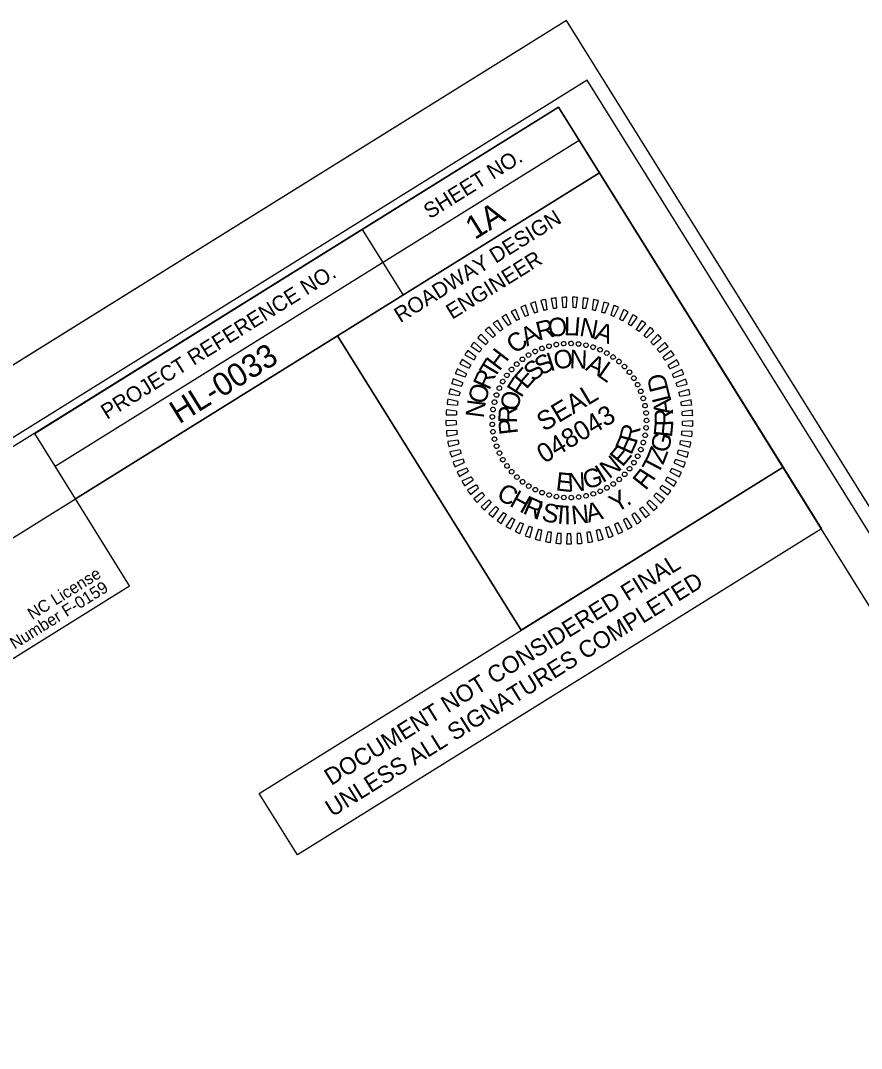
# Model space of a CAD drawing. Extents: x 2047559 to 2049567, y 759970 to 761789.
# Drawn here: x 2048811.1 to 2049083.6, y 761456 to 761789.3 of the extents above; entities that cross this region are included whole.
import ezdxf

# ---------------------------------------------------------------- set-up
doc = ezdxf.new("R2010")
doc.units = 0
for name, color, linetype in [('Default', 7, 'Continuous'), ('Old_Level_4', 7, 'Continuous'), ('Sheet Cutting Line CELL', 7, 'Continuous'), ('Sheet Data Field CELL', 7, 'Continuous'), ('Sheet PE Seal Cell', 7, 'Continuous'), ('Sheet Plan CELL', 7, 'Continuous'), ('Sheet Plot Border Inside CELL', 7, 'Continuous'), ('Sheet Plot Border Outside CELL', 7, 'Continuous'), ('Sheet Sticker Exception Certification CELL', 7, 'Continuous')]:
    doc.layers.add(name, color=color, linetype=linetype)

msp = doc.modelspace()

# ---------------------------------------------------------------- linework, layer by layer
at = {"layer": 'Default'}
msp.add_line((2048693.02, 761549.62), (2048828.87, 761634.21), dxfattribs=at)
at = {"layer": 'Old_Level_4'}
for p, q in [((2048846.4, 761606.07), (2048828.87, 761634.21)), ((2048710.56, 761521.46), (2048846.4, 761606.07))]:
    msp.add_line(p, q, dxfattribs=at)
at = {"layer": 'Sheet Cutting Line CELL'}
msp.add_line((2048987.97, 761789.33), (2047559, 760899.25), dxfattribs=at)
at = {"layer": 'Sheet PE Seal Cell'}
for p, q in [((2048975.68, 761693.81), (2048974.65, 761697.01)), ((2048976.34, 761697.61), (2048977.57, 761694.48)), ((2048978.67, 761694.82), (2048977.92, 761698.09)), ((2048979.65, 761698.55), (2048980.61, 761695.33)), ((2048981.73, 761695.57), (2048981.27, 761698.89)), ((2048983.03, 761699.2), (2048983.7, 761695.91)), ((2048984.85, 761696.06), (2048984.67, 761699.41)), ((2048986.46, 761699.56), (2048986.84, 761696.22)), ((2048987.99, 761696.27), (2048988.11, 761699.62)), ((2048989.9, 761699.62), (2048990, 761696.26)), ((2048991.14, 761696.21), (2048991.55, 761699.54)), ((2048993.33, 761699.39), (2048993.14, 761696.04)), ((2048994.28, 761695.88), (2048994.97, 761699.17)), ((2048996.73, 761698.86), (2048996.26, 761695.54)), ((2048997.38, 761695.29), (2048998.34, 761698.5)), ((2049000.08, 761698.04), (2048999.31, 761694.77)), ((2049000.41, 761694.43), (2049001.65, 761697.55)), ((2049003.34, 761696.94), (2049002.3, 761693.75)), ((2048970.02, 761691.04), (2048968.46, 761694.01)), ((2048970.02, 761694.89), (2048971.77, 761692.03)), ((2048972.79, 761692.55), (2048971.49, 761695.64)), ((2048973.13, 761696.39), (2048974.61, 761693.38)), ((2049003.36, 761693.31), (2049004.86, 761696.31)), ((2049006.49, 761695.56), (2049005.18, 761692.47)), ((2049006.2, 761691.94), (2049007.96, 761694.8)), ((2049009.51, 761693.91), (2049007.94, 761690.95)), ((2048964.92, 761687.34), (2048962.88, 761690)), ((2048964.26, 761691.14), (2048966.47, 761688.61)), ((2048967.39, 761689.3), (2048965.58, 761692.13)), ((2048967.06, 761693.14), (2048969.04, 761690.43)), ((2049008.92, 761690.34), (2049010.91, 761693.04)), ((2049012.38, 761692.02), (2049010.56, 761689.2)), ((2049011.48, 761688.5), (2049013.7, 761691.02)), ((2048962.63, 761685.18), (2048960.36, 761687.65)), ((2048961.65, 761688.9), (2048964.06, 761686.57)), ((2049015.08, 761689.88), (2049013.03, 761687.23)), ((2049013.88, 761686.46), (2049016.31, 761688.77)), ((2049017.59, 761687.52), (2049015.31, 761685.05)), ((2048957.03, 761683.8), (2048959.81, 761681.92)), ((2048960.53, 761682.82), (2048958.06, 761685.09)), ((2048959.23, 761686.45), (2048961.84, 761684.34)), ((2049016.09, 761684.21), (2049018.71, 761686.31)), ((2049019.88, 761684.95), (2049017.4, 761682.69)), ((2049018.11, 761681.78), (2049020.89, 761683.65)), ((2048955.07, 761680.97), (2048958.01, 761679.34)), ((2048958.64, 761680.3), (2048955.98, 761682.35)), ((2049021.94, 761682.19), (2049019.27, 761680.15)), ((2049019.9, 761679.19), (2049022.84, 761680.81)), ((2048953.37, 761677.98), (2048956.43, 761676.61)), ((2048956.97, 761677.62), (2048954.15, 761679.43)), ((2049023.75, 761679.27), (2049020.92, 761677.47)), ((2049021.47, 761676.45), (2049024.53, 761677.81)), ((2048951.92, 761674.86), (2048955.09, 761673.75)), ((2048955.55, 761674.81), (2048952.58, 761676.37)), ((2049025.31, 761676.2), (2049022.34, 761674.65)), ((2049022.79, 761673.59), (2049025.97, 761674.68)), ((2048950.75, 761671.62), (2048954, 761670.79)), ((2048954.36, 761671.88), (2048951.27, 761673.19)), ((2049026.6, 761673.01), (2049023.51, 761671.72)), ((2049023.87, 761670.63), (2049027.12, 761671.44)), ((2048949.86, 761668.3), (2048953.17, 761667.75)), ((2048953.44, 761668.87), (2048950.25, 761669.9)), ((2049027.61, 761669.72), (2049024.42, 761668.7)), ((2049024.68, 761667.58), (2049028, 761668.11)), ((2048949.26, 761664.91), (2048952.6, 761664.65)), ((2048952.78, 761665.78), (2048949.51, 761666.54)), ((2049028.34, 761666.35), (2049025.07, 761665.61)), ((2049025.24, 761664.47), (2049028.58, 761664.72)), ((2048948.95, 761661.48), (2048952.3, 761661.51)), ((2048952.38, 761662.66), (2048949.06, 761663.13)), ((2049028.77, 761662.94), (2049025.45, 761662.48)), ((2049025.52, 761661.33), (2049028.87, 761661.29)), ((2048952.26, 761659.51), (2048948.91, 761659.69)), ((2048948.94, 761658.04), (2048952.28, 761658.36)), ((2048988.91, 761659.63), (2048988.91, 761659.63)), ((2049025.53, 761658.18), (2049028.87, 761657.85)), ((2049028.91, 761659.5), (2049025.56, 761659.33)), ((2048952.4, 761656.35), (2048949.05, 761656.25)), ((2048949.22, 761654.61), (2048952.52, 761655.21)), ((2049025.27, 761655.04), (2049028.57, 761654.42)), ((2049028.75, 761656.06), (2049025.39, 761656.18)), ((2048952.82, 761653.23), (2048949.49, 761652.84)), ((2048949.8, 761651.22), (2048953.04, 761652.1)), ((2048953.5, 761650.15), (2048950.22, 761649.47)), ((2049027.55, 761649.29), (2049024.26, 761649.98)), ((2049024.74, 761651.93), (2049027.97, 761651.03)), ((2049028.29, 761652.65), (2049024.96, 761653.06)), ((2048950.67, 761647.89), (2048953.82, 761649.04)), ((2048954.45, 761647.14), (2048951.23, 761646.19)), ((2049026.51, 761646.01), (2049023.3, 761646.98)), ((2049023.94, 761648.88), (2049027.09, 761647.71)), ((2048951.82, 761644.64), (2048954.86, 761646.07)), ((2048955.65, 761644.23), (2048952.53, 761643)), ((2049025.2, 761642.82), (2049022.09, 761644.07)), ((2049022.89, 761645.9), (2049025.92, 761644.47)), ((2048953.25, 761641.51), (2048956.15, 761643.19)), ((2048957.1, 761641.42), (2048954.09, 761639.93)), ((2048954.94, 761638.51), (2048957.69, 761640.44)), ((2049020.04, 761640.29), (2049022.78, 761638.35)), ((2049023.63, 761639.77), (2049020.63, 761641.27)), ((2049021.58, 761643.03), (2049024.48, 761641.34)), ((2048958.78, 761638.76), (2048955.92, 761637.01)), ((2048956.88, 761635.67), (2048959.45, 761637.82)), ((2049018.26, 761637.68), (2049020.82, 761635.52)), ((2049021.79, 761636.86), (2049018.93, 761638.61)), ((2048960.69, 761636.25), (2048957.98, 761634.26)), ((2048959.05, 761633.01), (2048961.43, 761635.37)), ((2048962.8, 761633.91), (2048960.28, 761631.7)), ((2049017.4, 761631.56), (2049014.89, 761633.78)), ((2049016.26, 761635.24), (2049018.63, 761632.86)), ((2049019.71, 761634.11), (2049017.01, 761636.11)), ((2048961.45, 761630.54), (2048963.62, 761633.1)), ((2048965.11, 761631.76), (2048962.79, 761629.34)), ((2048964.06, 761628.29), (2048966, 761631.02)), ((2049011.68, 761630.92), (2049013.61, 761628.17)), ((2049014.88, 761629.21), (2049012.57, 761631.64)), ((2049014.06, 761632.98), (2049016.22, 761630.41)), ((2048967.59, 761629.81), (2048965.49, 761627.2)), ((2048966.84, 761626.27), (2048968.54, 761629.16)), ((2048970.24, 761628.09), (2048968.36, 761625.31)), ((2048969.79, 761624.49), (2048971.24, 761627.52)), ((2049006.42, 761627.44), (2049007.85, 761624.4)), ((2049009.29, 761625.21), (2049007.43, 761628)), ((2049009.13, 761629.06), (2049010.81, 761626.16)), ((2049012.17, 761627.09), (2049010.08, 761629.71)), ((2048973.02, 761626.6), (2048971.39, 761623.67)), ((2048972.88, 761622.98), (2048974.06, 761626.12)), ((2048975.91, 761625.36), (2048974.54, 761622.3)), ((2048976.09, 761621.74), (2048977, 761624.97)), ((2048978.91, 761624.37), (2048977.81, 761621.2)), ((2048979.4, 761620.78), (2048980.02, 761624.07)), ((2048981.98, 761623.64), (2048981.15, 761620.39)), ((2048982.77, 761620.1), (2048983.11, 761623.44)), ((2048994.53, 761623.42), (2048994.85, 761620.08)), ((2048996.48, 761620.35), (2048995.66, 761623.61)), ((2048997.62, 761624.03), (2048998.23, 761620.73)), ((2048999.82, 761621.15), (2048998.74, 761624.32)), ((2049000.65, 761624.91), (2049001.54, 761621.68)), ((2049003.09, 761622.23), (2049001.73, 761625.3)), ((2049003.59, 761626.05), (2049004.75, 761622.9)), ((2049006.25, 761623.59), (2049004.64, 761626.53)), ((2048985.1, 761623.18), (2048984.55, 761619.87)), ((2048986.2, 761619.72), (2048986.24, 761623.08)), ((2048988.24, 761622.99), (2048987.99, 761619.64)), ((2048989.64, 761619.64), (2048989.39, 761622.98)), ((2048991.4, 761623.07), (2048991.43, 761619.71)), ((2048993.07, 761619.85), (2048992.54, 761623.16))]:
    msp.add_line(p, q, dxfattribs=at)
for radius, start, end in [(40, 110.8732, 113.2368), (40, 105.9417, 108.3053), (40, 101.0102, 103.3738), (40, 96.0787, 98.4423), (40, 91.1472, 93.5108), (40, 86.2157, 88.5793), (40, 81.2842, 83.6478), (40, 76.3527, 78.7163), (40, 71.4212, 73.7848), (40, 66.4896, 68.8533), (40, 120.7362, 123.0998), (40, 115.8047, 118.1683), (36.65, 111.1561, 112.954), (36.65, 106.2246, 108.0225), (36.65, 101.2931, 103.091), (36.65, 96.3616, 98.1594), (36.65, 91.43, 93.2279), (36.65, 86.4985, 88.2964), (36.65, 81.567, 83.3649), (36.65, 76.6355, 78.4334), (36.65, 71.704, 73.5019), (36.65, 66.7725, 68.5704), (40, 61.5581, 63.9218), (40, 56.6266, 58.9903), (40, 130.5992, 132.9629), (40, 125.6677, 128.0313), (36.65, 121.0191, 122.817), (36.65, 116.0876, 117.8855), (36.65, 61.841, 63.6389), (36.65, 56.9095, 58.7074), (40, 51.6951, 54.0587), (40, 135.5307, 137.8944), (36.65, 130.8821, 132.68), (36.65, 125.9506, 127.7485), (36.65, 51.978, 53.7759), (36.65, 47.0465, 48.8444), (40, 46.7636, 49.1272), (40, 41.8321, 44.1957), (40, 140.4623, 142.8259), (36.65, 135.8136, 137.6115), (36.65, 42.115, 43.9129), (40, 36.9006, 39.2642), (40, 145.3938, 147.7574), (36.65, 145.6766, 147.4745), (36.65, 140.7451, 142.543), (36.65, 37.1835, 38.9814), (36.65, 32.252, 34.0499), (40, 31.9691, 34.3327), (40, 150.3253, 152.6889), (36.65, 150.6081, 152.406), (36.65, 27.3205, 29.1184), (40, 27.0376, 29.4012), (40, 155.2568, 157.6204), (36.65, 155.5396, 157.3375), (36.65, 22.3889, 24.1868), (40, 22.1061, 24.4697), (40, 160.1883, 162.5519), (36.65, 160.4711, 162.269), (36.65, 17.4574, 19.2553), (40, 17.1746, 19.5382), (40, 165.1198, 167.4834), (36.65, 165.4026, 167.2005), (36.65, 12.5259, 14.3238), (40, 12.2431, 14.6067), (40, 170.0513, 172.4149), (36.65, 170.3342, 172.132), (36.65, 7.5944, 9.3923), (40, 7.3116, 9.6752), (40, 174.9828, 177.3464), (36.65, 175.2657, 177.0636), (36.65, 2.6629, 4.4608), (40, 2.3801, 4.7437), (40, 179.9143, 182.2779), (36.65, 180.1972, 181.9951), (36.65, 357.7314, 359.5293), (40, 357.4486, 359.8122), (40, 184.8458, 187.2094), (36.65, 185.1287, 186.9266), (36.65, 352.7999, 354.5978), (40, 352.517, 354.8807), (40, 189.7773, 192.1409), (36.65, 190.0602, 191.8581), (36.65, 194.9917, 196.7896), (36.65, 342.9369, 344.7348), (36.65, 347.8684, 349.6663), (40, 347.5855, 349.9492), (40, 194.7088, 197.0724), (36.65, 199.9232, 201.7211), (36.65, 338.0054, 339.8033), (40, 342.654, 345.0177), (40, 199.6403, 202.004), (36.65, 204.8547, 206.6526), (36.65, 333.0739, 334.8718), (40, 337.7225, 340.0861), (40, 204.5718, 206.9355), (36.65, 209.7862, 211.5841), (36.65, 328.1424, 329.9403), (40, 332.791, 335.1546), (40, 209.5033, 211.867), (40, 214.4349, 216.7985), (36.65, 214.7177, 216.5156), (36.65, 323.2109, 325.0088), (40, 322.928, 325.2916), (40, 327.8595, 330.2231), (40, 219.3664, 221.73), (36.65, 219.6492, 221.4471), (36.65, 224.5807, 226.3786), (36.65, 313.3479, 315.1457), (36.65, 318.2794, 320.0773), (40, 317.9965, 320.3601), (40, 224.2979, 226.6615), (36.65, 229.5122, 231.3101), (36.65, 308.4163, 310.2142), (40, 313.065, 315.4286), (40, 229.2294, 231.593), (40, 234.1609, 236.5245), (36.65, 234.4437, 236.2416), (36.65, 239.3753, 241.1731), (36.65, 298.5533, 300.3512), (36.65, 303.4848, 305.2827), (40, 303.202, 305.5656), (40, 308.1335, 310.4971), (40, 239.0924, 241.456), (40, 244.0239, 246.3875), (36.65, 244.3068, 246.1047), (36.65, 249.2383, 251.0362), (36.65, 254.1698, 255.9677), (36.65, 259.1013, 260.8992), (36.65, 278.8273, 280.6252), (36.65, 283.7588, 285.5567), (36.65, 288.6903, 290.4882), (36.65, 293.6218, 295.4197), (40, 293.339, 295.7026), (40, 298.2705, 300.6341), (40, 248.9554, 251.319), (40, 253.8869, 256.2505), (40, 258.8184, 261.182), (36.65, 264.0328, 265.8307), (36.65, 268.9643, 270.7622), (36.65, 273.8958, 275.6937), (40, 278.5444, 280.9081), (40, 283.4759, 285.8396), (40, 288.4075, 290.7711), (40, 263.7499, 266.1135), (40, 268.6814, 271.045), (40, 273.6129, 275.9766)]:
    msp.add_arc((2048988.91, 761659.63), radius, start, end, dxfattribs=at)
for centre, major_axis in [((2048980.01, 761683), (-0.312, 0.674)), ((2048982.31, 761683.74), (-0.245, 0.701)), ((2048984.67, 761684.27), (-0.177, 0.721)), ((2048987.06, 761684.56), (-0.106, 0.735)), ((2048989.48, 761684.62), (-0.035, 0.742)), ((2048991.89, 761684.45), (0.037, 0.741)), ((2048994.27, 761684.05), (0.108, 0.734)), ((2048996.6, 761683.42), (0.179, 0.721)), ((2048998.86, 761682.56), (0.247, 0.7)), ((2048973.7, 761679.48), (-0.491, 0.556)), ((2048975.69, 761680.85), (-0.435, 0.601)), ((2048977.8, 761682.03), (-0.375, 0.64)), ((2049001.03, 761681.5), (0.314, 0.673)), ((2049003.08, 761680.22), (0.377, 0.639)), ((2048970.17, 761676.19), (-0.589, 0.452)), ((2048971.86, 761677.92), (-0.543, 0.506)), ((2049005, 761678.76), (0.437, 0.6)), ((2049006.77, 761677.12), (0.493, 0.555)), ((2048968.66, 761674.3), (-0.63, 0.393)), ((2049008.38, 761675.31), (0.544, 0.505)), ((2049009.8, 761673.36), (0.59, 0.45)), ((2048966.22, 761670.14), (-0.694, 0.264)), ((2048967.34, 761672.28), (-0.665, 0.33)), ((2049011.03, 761671.28), (0.631, 0.391)), ((2048965.31, 761667.9), (-0.716, 0.196)), ((2049012.05, 761669.09), (0.666, 0.328)), ((2049012.85, 761666.81), (0.694, 0.262)), ((2048964.16, 761663.21), (-0.74, 0.055)), ((2048964.63, 761665.58), (-0.732, 0.126)), ((2049013.43, 761664.47), (0.717, 0.194)), ((2048963.93, 761660.81), (-0.742, -0.017)), ((2049013.79, 761662.08), (0.732, 0.124)), ((2049013.91, 761659.66), (0.74, 0.053)), ((2048963.94, 761658.39), (-0.737, -0.088)), ((2048964.17, 761655.99), (-0.725, -0.159)), ((2049013.79, 761657.25), (0.742, -0.019)), ((2048964.64, 761653.62), (-0.706, -0.228)), ((2049012.87, 761652.51), (0.725, -0.161)), ((2049013.45, 761654.86), (0.737, -0.091)), ((2048965.33, 761651.3), (-0.681, -0.295)), ((2049012.07, 761650.23), (0.706, -0.23)), ((2048966.25, 761649.07), (-0.649, -0.36)), ((2048967.37, 761646.93), (-0.612, -0.421)), ((2049009.84, 761645.96), (0.648, -0.362)), ((2049011.06, 761648.04), (0.68, -0.297)), ((2048968.7, 761644.91), (-0.568, -0.478)), ((2048970.21, 761643.03), (-0.519, -0.53)), ((2049008.42, 761644), (0.61, -0.423)), ((2048971.9, 761641.3), (-0.466, -0.578)), ((2048973.75, 761639.75), (-0.408, -0.62)), ((2049005.05, 761640.54), (0.518, -0.532)), ((2049006.82, 761642.19), (0.567, -0.479)), ((2048975.74, 761638.38), (-0.346, -0.657)), ((2048977.85, 761637.21), (-0.281, -0.687)), ((2048980.07, 761636.24), (-0.213, -0.711)), ((2048996.66, 761635.86), (0.279, -0.688)), ((2048998.92, 761636.72), (0.344, -0.658)), ((2049001.08, 761637.8), (0.406, -0.622)), ((2049003.13, 761639.07), (0.464, -0.579)), ((2048982.37, 761635.5), (-0.144, -0.728)), ((2048984.73, 761634.98), (-0.073, -0.739)), ((2048987.13, 761634.69), (-0.001, -0.742)), ((2048989.54, 761634.64), (0.071, -0.739)), ((2048991.95, 761634.82), (0.142, -0.729)), ((2048994.33, 761635.23), (0.211, -0.712))]:
    msp.add_ellipse(centre, major_axis=major_axis, ratio=0.999708, dxfattribs=at)
at = {"layer": 'Sheet Plan CELL'}
for p, q in [((2048822.27, 761644.82), (2048992.07, 761750.59)), ((2048828.87, 761634.21), (2048998.68, 761739.98)), ((2048828.87, 761634.21), (2048998.68, 761739.98)), ((2048921.8, 761721.55), (2048935.02, 761700.33)), ((2048913.8, 761687.11), (2048973.25, 761591.66))]:
    msp.add_line(p, q, dxfattribs=at)
for points in [[(2048985.43, 761761.24), (2047712.23, 760968.18), (2048267.37, 760076.94), (2049540.57, 760870)], [(2048815.63, 761655.48), (2048985.43, 761761.24), (2048998.68, 761739.98), (2048828.87, 761634.21)], [(2048913.8, 761687.11), (2048998.68, 761739.98), (2049058.16, 761644.49), (2048973.28, 761591.62)]]:
    msp.add_lwpolyline(points, close=True, dxfattribs=at)
at = {"layer": 'Sheet Plot Border Inside CELL'}
msp.add_lwpolyline([(2048138.4, 759993.66), (2049552.51, 760874.48), (2048994.72, 761769.97), (2047580.61, 760889.15)], close=True, dxfattribs=at)
at = {"layer": 'Sheet Plot Border Outside CELL'}
msp.add_lwpolyline([(2048137.94, 759969.81), (2049566.9, 760859.89), (2048987.97, 761789.33), (2047559, 760899.25)], close=True, dxfattribs=at)
at = {"layer": 'Sheet Sticker Exception Certification CELL'}
for p, q in [((2048888.36, 761538.74), (2049058.15, 761644.5)), ((2049058.16, 761644.49), (2049070.58, 761624.54)), ((2049070.58, 761624.55), (2048900.78, 761518.79)), ((2048900.78, 761518.79), (2048888.36, 761538.74))]:
    msp.add_line(p, q, dxfattribs=at)

# ---------------------------------------------------------------- texts
at = {"layer": 'Default'}
for s, p in [('NC License', (2048814.85, 761594.87)), ('Number F-0159', (2048809.13, 761585.34))]:
    msp.add_text(s, height=3.865, rotation=31.9169, dxfattribs=at).set_placement(p)
at = {"layer": 'Sheet Data Field CELL'}
for s, p in [('1A ', (2048958.25, 761718.1)), ('HL-0033', (2048862.45, 761658.37))]:
    msp.add_text(s, height=7.5, rotation=31.918, dxfattribs=at).set_placement(p)
at = {"layer": 'Sheet PE Seal Cell'}
for s, height, rotation, p in [('A', 6, 29.3259, (2048975.18, 761683.55)), ('R', 6, 13.8387, (2048978.91, 761685.55)), ('O', 6, 6.5494, (2048982.3, 761686.64)), ('L', 6, 359.3492, (2048987.1, 761687.26)), ('I', 6, 355.3615, (2048990.17, 761687.24)), ('N', 6, 349.525, (2048991.91, 761687.16)), ('A', 6, 340.5947, (2048996.77, 761686.14)), ('C', 6, 38.2103, (2048971.41, 761680.98)), ('H', 6, 52.5792, (2048966.22, 761675.42)), ('S', 6, 31.9234, (2048979.98, 761674.04)), ('I', 6, 17.7635, (2048982.71, 761675.49)), ('O', 6, 9.3736, (2048984.29, 761676.1)), ('N', 6, 357.6601, (2048988.86, 761676.61)), ('A', 6, 335.1398, (2048993.83, 761676.07)), ('T', 6, 58.9723, (2048964.58, 761672.78)), ('E', 6, 49.1027, (2048974.97, 761669.5)), ('S', 6, 40.3036, (2048977.24, 761672.02)), ('L', 6, 325.0067, (2048997.66, 761674.25)), ('R', 6, 66.0693, (2048962.96, 761669.24)), ('F', 6, 57.3299, (2048973.32, 761666.75)), ('D', 6, 103.9701, (2049021.04, 761669.76)), ('O', 6, 73.7319, (2048961.6, 761664.62)), ('SEAL', 6.184, 30.918, (2048980.67, 761655.9)), ('L', 6, 103.9701, (2049021.89, 761666.34)), ('O', 6, 76.2776, (2048972.09, 761662.36)), ('A', 6, 97.8539, (2049022.55, 761661.84)), ('N', 6, 82.7516, (2048961.16, 761660.24)), ('R', 6, 88.2039, (2048971.87, 761658.66)), ('048043', 6.185, 30.918, (2048980.75, 761645.56)), ('R', 6, 91.0316, (2049022.57, 761657.83)), ('P', 6, 96.7111, (2048972.31, 761655.4)), ('R', 6, 74.9157, (2049010.66, 761651.95)), ('E', 6, 84.457, (2049022.14, 761653.99)), ('E', 6, 66.1627, (2049008.97, 761648.21)), ('G', 6, 75.4664, (2049020.85, 761648.86)), ('E', 6, 49.7591, (2049006.07, 761644.33)), ('Z', 6, 68.4995, (2049019.31, 761645.07)), ('N', 6, 38.9099, (2049001.83, 761640.51)), ('T', 6, 62.1314, (2049017.51, 761641.78)), ('G', 6, 15.8756, (2048994.24, 761637.26)), ('I', 6, 31.4603, (2048999.64, 761639.26)), ('F', 6, 51.2537, (2049013.62, 761636.71)), ('I', 6, 57.7663, (2049016.06, 761639.66)), ('E', 6, 353.4924, (2048984.31, 761637.02)), ('N', 6, 3.3459, (2048988.51, 761636.57)), ('C', 6, 331.1541, (2048964.96, 761634.43)), ('H', 6, 331.1541, (2048969.19, 761632.1)), ('Y', 6, 30.9827, (2049004.15, 761629.56)), ('R', 6, 336.9819, (2048973.53, 761629.63)), ('I', 6, 343.8043, (2048977.2, 761628.02)), ('.', 6, 38.0942, (2049007.75, 761631.68)), ('S', 6, 348.1694, (2048979.64, 761627.22)), ('T', 6, 354.8886, (2048983.5, 761626.36)), ('I', 6, 1.2566, (2048987.23, 761625.96)), ('N', 6, 5.6217, (2048989.79, 761625.93)), ('A', 6, 14.6123, (2048995.05, 761626.49))]:
    msp.add_text(s, height=height, rotation=rotation, dxfattribs=at).set_placement(p)
at = {"layer": 'Sheet Plan CELL'}
for s, height, p in [('SHEET NO.', 5, (2048943.66, 761724.85)), ('ROADWAY DESIGN', 5.0001, (2048934.12, 761691.17)), ('ENGINEER', 5, (2048950.93, 761692.27)), ('PROJECT REFERENCE NO.', 5.0001, (2048839.07, 761659.83))]:
    msp.add_text(s, height=height, rotation=31.918, dxfattribs=at).set_placement(p)
at = {"layer": 'Sheet Sticker Exception Certification CELL'}
for s, p in [('DOCUMENT NOT CONSIDERED FINAL', (2048911.71, 761541.1)), ('UNLESS ALL SIGNATURES COMPLETED', (2048912.06, 761530.95))]:
    msp.add_text(s, height=5.5, rotation=31.918, dxfattribs=at).set_placement(p)

doc.saveas('drawing.dxf')
